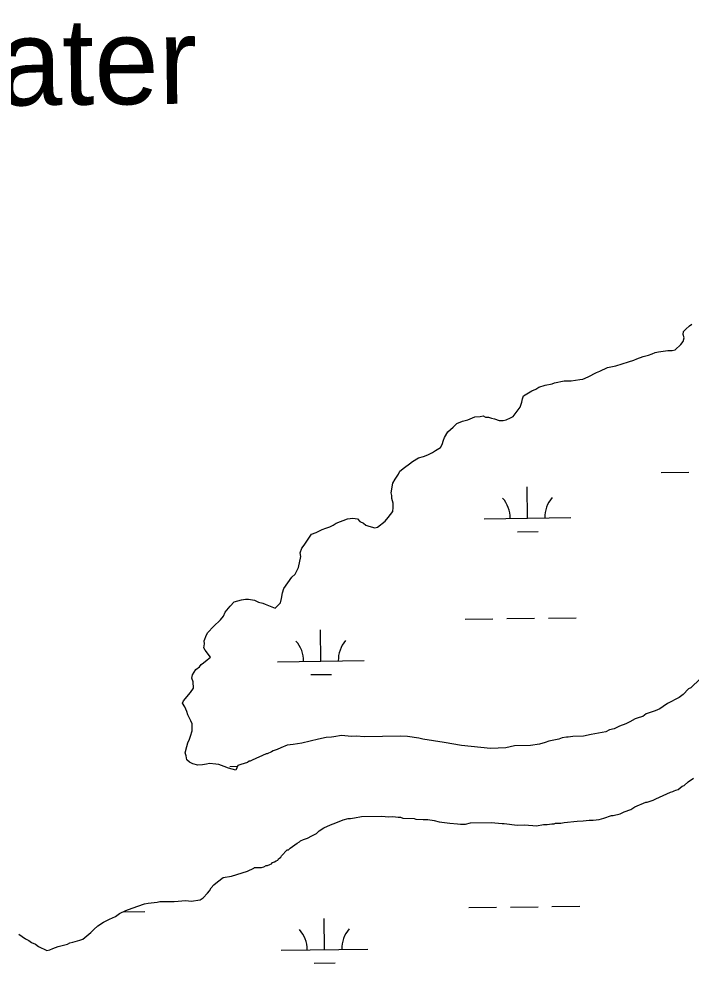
# Model space of a CAD drawing. Extents: x 3702978 to 3741108, y 397120 to 422907.
# Drawn here: x 3712893 to 3713669, y 405307 to 406396 of the extents above; entities that cross this region are included whole.
import ezdxf

# ---------------------------------------------------------------- set-up
doc = ezdxf.new("R2010")
doc.units = 0
for name, color, linetype in [('V-RIVR-IDEN', 7, 'Continuous'), ('V-TOPO-SHOR', 7, 'Continuous'), ('V-WETL-SWMP', 7, 'Continuous')]:
    doc.layers.add(name, color=color, linetype=linetype)

msp = doc.modelspace()

# ---------------------------------------------------------------- linework, layer by layer
at = {"layer": 'V-TOPO-SHOR'}
for points in [[(3713360.082, 405891.456), (3713364.814, 405893.586), (3713370.215, 405896.409), (3713373.585, 405898.514), (3713379.655, 405902.03), (3713381.638, 405905.473), (3713382.915, 405910.266), (3713384.216, 405913.697), (3713388.194, 405919.902), (3713394.227, 405925.462), (3713398.241, 405929.623), (3713405.005, 405932.47), (3713411.112, 405933.943), (3713419.226, 405937.496), (3713425.357, 405937.606), (3713428.751, 405938.349), (3713431.501, 405937.035), (3713434.907, 405937.096), (3713438.338, 405935.795), (3713441.757, 405935.175), (3713447.243, 405933.229), (3713452.012, 405933.314), (3713455.406, 405934.057), (3713460.139, 405936.186), (3713463.52, 405937.61), (3713471.5, 405948.657), (3713473.446, 405954.144), (3713474.054, 405958.244), (3713475.355, 405961.674), (3713484.795, 405967.296), (3713489.527, 405969.425), (3713492.897, 405971.53), (3713500.354, 405973.709), (3713508.505, 405975.218), (3713511.205, 405976.629), (3713522.069, 405978.869), (3713530.244, 405979.016), (3713540.438, 405980.562), (3713543.845, 405980.623), (3713549.927, 405983.458), (3713559.379, 405988.398), (3713563.442, 405989.834), (3713572.225, 405994.081), (3713581.726, 405996.296), (3713596.641, 406000.652), (3713602.736, 406002.806), (3713606.117, 406004.23), (3713613.562, 406007.089), (3713619.669, 406008.562), (3713623.732, 406009.998), (3713627.114, 406011.422), (3713631.19, 406012.176), (3713642.065, 406013.735), (3713646.834, 406013.82), (3713650.228, 406014.563), (3713656.931, 406020.816), (3713659.595, 406024.272), (3713660.884, 406028.384), (3713659.448, 406032.447), (3713660.068, 406035.865), (3713662.744, 406038.639), (3713666.771, 406042.119), (3713669.459, 406044.212)], [(3713143.293, 405529.863), (3713134.825, 405532.359), (3713130.02, 405534.317), (3713123.851, 405536.251), (3713120.433, 405536.871), (3713112.927, 405537.417), (3713109.533, 405536.675), (3713104.776, 405535.908), (3713099.326, 405535.81), (3713093.851, 405537.075), (3713089.727, 405539.045), (3713086.953, 405541.721), (3713086.186, 405546.478), (3713084.763, 405549.86), (3713086.672, 405557.391), (3713087.961, 405561.503), (3713089.931, 405565.627), (3713091.233, 405569.058), (3713093.166, 405575.226), (3713093.02, 405583.401), (3713091.596, 405586.783), (3713088.067, 405593.534), (3713086.631, 405597.597), (3713084.49, 405603.011), (3713081.691, 405607.049), (3713083.005, 405609.799), (3713091.009, 405619.483), (3713094.329, 405624.313), (3713094.195, 405631.807), (3713092.759, 405635.871), (3713093.367, 405639.97), (3713097.344, 405646.175), (3713101.383, 405648.974), (3713103.378, 405651.735), (3713106.066, 405653.828), (3713110.093, 405657.308), (3713114.131, 405660.106), (3713107.853, 405668.171), (3713106.442, 405670.872), (3713107.037, 405675.653), (3713106.976, 405679.059), (3713109.579, 405685.921), (3713110.893, 405688.67), (3713117.583, 405695.605), (3713125.623, 405703.246), (3713128.956, 405707.395), (3713130.915, 405712.2), (3713136.924, 405719.123), (3713141.607, 405723.978), (3713149.745, 405726.168), (3713154.502, 405726.935), (3713157.908, 405726.996), (3713164.745, 405725.756), (3713169.551, 405723.798), (3713174.344, 405722.521), (3713177.094, 405721.207), (3713188.761, 405716.646), (3713194.782, 405722.888), (3713196.059, 405727.681), (3713197.299, 405734.518), (3713198.576, 405739.312), (3713207.881, 405752.427), (3713211.908, 405755.907), (3713215.861, 405763.474), (3713218.354, 405776.467), (3713217.599, 405780.542), (3713219.545, 405786.029), (3713222.209, 405789.484), (3713230.845, 405801.906), (3713236.258, 405804.048), (3713243.01, 405807.576), (3713247.073, 405809.012), (3713251.817, 405810.46), (3713255.868, 405812.578), (3713259.238, 405814.682), (3713272.096, 405819.684), (3713278.215, 405820.475), (3713283.678, 405819.892), (3713286.464, 405816.534), (3713290.588, 405814.564), (3713293.35, 405812.569), (3713296.781, 405811.268), (3713303.63, 405809.346), (3713307.024, 405810.089), (3713315.758, 405817.06), (3713319.091, 405821.209), (3713324.419, 405828.12), (3713325.015, 405832.901), (3713324.929, 405837.669), (3713323.469, 405843.095), (3713323.408, 405846.501), (3713322.665, 405849.895), (3713324.513, 405860.832), (3713327.153, 405865.65), (3713331.142, 405871.174), (3713332.444, 405874.604), (3713337.821, 405878.79), (3713343.879, 405882.988), (3713347.236, 405885.774), (3713353.975, 405889.984), (3713360.082, 405891.456)], [(3713679.025, 405635.4), (3713668.308, 405624.986), (3713665.608, 405623.574), (3713659.586, 405617.333), (3713654.879, 405613.841), (3713641.376, 405606.784), (3713636.668, 405603.292), (3713632.629, 405600.493), (3713627.216, 405598.351), (3713617.058, 405594.762), (3713613.02, 405591.963), (3713608.956, 405590.527), (3713604.212, 405589.079), (3713598.142, 405585.563), (3713593.41, 405583.433), (3713585.965, 405580.574), (3713579.882, 405577.739), (3713574.457, 405576.278), (3713570.406, 405574.161), (3713553.423, 405571.13), (3713544.603, 405568.927), (3713532.341, 405568.707), (3713526.903, 405567.928), (3713524.859, 405567.891), (3713520.102, 405567.124), (3713516.039, 405565.689), (3713504.494, 405563.437), (3713500.431, 405562.001), (3713493.655, 405559.835), (3713483.461, 405558.289), (3713465.067, 405557.958), (3713454.884, 405555.731), (3713437.184, 405554.732), (3713403.728, 405558.22), (3713383.898, 405561.953), (3713359.299, 405565.6), (3713354.506, 405566.877), (3713341.525, 405568.689), (3713333.338, 405569.223), (3713291.781, 405568.477), (3713282.231, 405568.987), (3713276.781, 405568.889), (3713265.175, 405570.044), (3713256.343, 405568.522), (3713253.63, 405567.792), (3713247.499, 405567.682), (3713238.679, 405565.479), (3713219.677, 405561.049), (3713209.482, 405559.503), (3713202.682, 405558.699), (3713195.237, 405555.84), (3713191.186, 405553.722), (3713186.442, 405552.274), (3713184.422, 405550.875), (3713179.69, 405548.746), (3713178.328, 405548.721), (3713162.1, 405541.615), (3713160.08, 405540.216), (3713158.718, 405540.191), (3713156.699, 405538.792), (3713149.241, 405536.614), (3713145.859, 405535.19), (3713143.293, 405529.863)], [(3713226.22, 405451.393), (3713230.94, 405454.203), (3713236.341, 405457.026), (3713239.698, 405459.813), (3713245.087, 405463.317), (3713252.52, 405466.858), (3713258.615, 405469.012), (3713267.41, 405472.577), (3713272.836, 405474.037), (3713275.561, 405474.086), (3713280.317, 405474.853), (3713288.468, 405476.362), (3713311.631, 405476.778), (3713319.819, 405476.244), (3713324.587, 405476.329), (3713330.731, 405475.758), (3713333.456, 405475.807), (3713336.206, 405474.494), (3713349.162, 405474.045), (3713351.218, 405473.4), (3713359.405, 405472.866), (3713364.855, 405472.964), (3713372.374, 405471.736), (3713377.848, 405470.471), (3713390.148, 405468.647), (3713399.016, 405468.125), (3713402.435, 405467.505), (3713408.566, 405467.615), (3713413.992, 405469.075), (3713437.836, 405469.504), (3713450.805, 405468.373), (3713452.849, 405468.41), (3713467.873, 405466.635), (3713476.048, 405466.782), (3713486.279, 405466.284), (3713490.379, 405465.677), (3713498.53, 405467.186), (3713502.618, 405467.259), (3713508.055, 405468.038), (3713510.78, 405468.087), (3713512.131, 405468.793), (3713518.262, 405468.903), (3713522.337, 405469.658), (3713537.301, 405471.289), (3713544.113, 405471.412), (3713550.914, 405472.215), (3713555.683, 405472.301), (3713562.483, 405473.104), (3713567.909, 405474.565), (3713576.716, 405477.449), (3713578.76, 405477.486), (3713586.899, 405479.676), (3713591.631, 405481.806), (3713599.076, 405484.665), (3713603.796, 405487.476), (3713616.642, 405493.158), (3713618.004, 405493.183), (3713622.749, 405494.631), (3713624.78, 405495.349), (3713628.162, 405496.773), (3713645.059, 405504.572), (3713647.772, 405505.303), (3713649.122, 405506.008), (3713651.154, 405506.726), (3713653.867, 405507.456), (3713658.562, 405511.63), (3713660.594, 405512.348), (3713665.289, 405516.521), (3713671.347, 405520.719)], [(3712892.934, 405340.608), (3712900.525, 405335.292), (3712904.65, 405333.322), (3712907.412, 405331.327), (3712912.217, 405329.369), (3712915.672, 405326.705), (3712925.296, 405322.107), (3712928.69, 405322.849), (3712932.072, 405324.273), (3712938.166, 405326.427), (3712949.018, 405329.348), (3712951.718, 405330.759), (3712955.112, 405331.502), (3712963.251, 405333.692), (3712966.633, 405335.116), (3712976.036, 405342.781), (3712979.381, 405346.249), (3712984.076, 405350.422), (3712990.816, 405354.632), (3712997.567, 405358.16), (3713004.331, 405361.008), (3713009.038, 405364.5), (3713016.471, 405368.041), (3713023.916, 405370.9), (3713038.137, 405375.926), (3713042.213, 405376.681), (3713052.419, 405377.545), (3713055.813, 405378.288), (3713072.164, 405378.581), (3713085.777, 405379.507), (3713091.92, 405378.936), (3713102.115, 405380.482), (3713105.484, 405382.587), (3713110.837, 405388.135), (3713112.832, 405390.897), (3713114.814, 405394.34), (3713118.159, 405397.807), (3713122.186, 405401.287), (3713128.913, 405406.178), (3713138.426, 405407.712), (3713156.722, 405413.492), (3713164.155, 405417.033), (3713164.894, 405417.646), (3713172.987, 405417.726), (3713175.7, 405418.456), (3713178.401, 405419.867), (3713179.763, 405419.892), (3713182.464, 405421.303), (3713184.495, 405422.021), (3713185.833, 405423.408), (3713187.865, 405424.126), (3713189.884, 405425.525), (3713191.916, 405426.243), (3713192.573, 405427.618), (3713195.261, 405429.711), (3713195.918, 405431.086), (3713202.608, 405438.021), (3713203.971, 405438.045), (3713205.978, 405440.126), (3713214.055, 405445.723), (3713216.756, 405447.134), (3713218.094, 405448.521), (3713221.476, 405449.945), (3713226.22, 405451.393)]]:
    msp.add_lwpolyline(points, dxfattribs=at)
at = {"layer": 'V-WETL-SWMP'}
for p, q in [((3713634.005, 405873.133), (3713666.002, 405873.53)), ((3713480.055, 405820.474), (3713479.608, 405856.472)), ((3713430.059, 405819.853), (3713530.051, 405821.095)), ((3713468.248, 405804.896), (3713492.246, 405805.194)), ((3713408.086, 405704.14), (3713440.084, 405704.537)), ((3713456.083, 405704.736), (3713488.08, 405705.133)), ((3713504.079, 405705.332), (3713536.077, 405705.729)), ((3713241.612, 405655.638), (3713241.165, 405691.635)), ((3713191.616, 405655.017), (3713291.608, 405656.259)), ((3713229.805, 405640.059), (3713253.803, 405640.357)), ((3713136.268, 405534.249), (3713145.461, 405534.363)), ((3713013.309, 405366.534), (3713038.34, 405366.845)), ((3713412.219, 405371.49), (3713444.216, 405371.887)), ((3713460.215, 405372.086), (3713492.213, 405372.483)), ((3713508.211, 405372.682), (3713540.209, 405373.08)), ((3713245.744, 405322.988), (3713245.297, 405358.985)), ((3713195.748, 405322.367), (3713295.741, 405323.609)), ((3713233.937, 405307.409), (3713257.935, 405307.707))]:
    msp.add_line(p, q, dxfattribs=at)
for points in [[(3713360.082, 405891.456), (3713364.814, 405893.586), (3713370.215, 405896.409), (3713373.585, 405898.514), (3713379.655, 405902.03), (3713381.638, 405905.473), (3713382.915, 405910.266), (3713384.216, 405913.697), (3713388.194, 405919.902), (3713394.227, 405925.462), (3713398.241, 405929.623), (3713405.005, 405932.47), (3713411.112, 405933.943), (3713419.226, 405937.496), (3713425.357, 405937.606), (3713428.751, 405938.349), (3713431.501, 405937.035), (3713434.907, 405937.096), (3713438.338, 405935.795), (3713441.757, 405935.175), (3713447.243, 405933.229), (3713452.012, 405933.314), (3713455.406, 405934.057), (3713460.139, 405936.186), (3713463.52, 405937.61), (3713471.5, 405948.657), (3713473.446, 405954.144), (3713474.054, 405958.244), (3713475.355, 405961.674), (3713484.795, 405967.296), (3713489.527, 405969.425), (3713492.897, 405971.53), (3713500.354, 405973.709), (3713508.505, 405975.218), (3713511.205, 405976.629), (3713522.069, 405978.869), (3713530.244, 405979.016), (3713540.438, 405980.562), (3713543.845, 405980.623), (3713549.927, 405983.458), (3713559.379, 405988.398), (3713563.442, 405989.834), (3713572.225, 405994.081), (3713581.726, 405996.296), (3713596.641, 406000.652), (3713602.736, 406002.806), (3713606.117, 406004.23), (3713613.562, 406007.089), (3713619.669, 406008.562), (3713623.732, 406009.998), (3713627.114, 406011.422), (3713631.19, 406012.176), (3713642.065, 406013.735), (3713646.834, 406013.82), (3713650.228, 406014.563), (3713656.931, 406020.816), (3713659.595, 406024.272), (3713660.884, 406028.384), (3713659.448, 406032.447), (3713660.068, 406035.865), (3713662.744, 406038.639), (3713666.771, 406042.119), (3713669.459, 406044.212)], [(3713143.293, 405529.863), (3713134.825, 405532.359), (3713130.02, 405534.317), (3713123.851, 405536.251), (3713120.433, 405536.871), (3713112.927, 405537.417), (3713109.533, 405536.675), (3713104.776, 405535.908), (3713099.326, 405535.81), (3713093.851, 405537.075), (3713089.727, 405539.045), (3713086.953, 405541.721), (3713086.186, 405546.478), (3713084.763, 405549.86), (3713086.672, 405557.391), (3713087.961, 405561.503), (3713089.931, 405565.627), (3713091.233, 405569.058), (3713093.166, 405575.226), (3713093.02, 405583.401), (3713091.596, 405586.783), (3713088.067, 405593.534), (3713086.631, 405597.597), (3713084.49, 405603.011), (3713081.691, 405607.049), (3713083.005, 405609.799), (3713091.009, 405619.483), (3713094.329, 405624.313), (3713094.195, 405631.807), (3713092.759, 405635.871), (3713093.367, 405639.97), (3713097.344, 405646.175), (3713101.383, 405648.974), (3713103.378, 405651.735), (3713106.066, 405653.828), (3713110.093, 405657.308), (3713114.131, 405660.106), (3713107.853, 405668.171), (3713106.442, 405670.872), (3713107.037, 405675.653), (3713106.976, 405679.059), (3713109.579, 405685.921), (3713110.893, 405688.67), (3713117.583, 405695.605), (3713125.623, 405703.246), (3713128.956, 405707.395), (3713130.915, 405712.2), (3713136.924, 405719.123), (3713141.607, 405723.978), (3713149.745, 405726.168), (3713154.502, 405726.935), (3713157.908, 405726.996), (3713164.745, 405725.756), (3713169.551, 405723.798), (3713174.344, 405722.521), (3713177.094, 405721.207), (3713188.761, 405716.646), (3713194.782, 405722.888), (3713196.059, 405727.681), (3713197.299, 405734.518), (3713198.576, 405739.312), (3713207.881, 405752.427), (3713211.908, 405755.907), (3713215.861, 405763.474), (3713218.354, 405776.467), (3713217.599, 405780.542), (3713219.545, 405786.029), (3713222.209, 405789.484), (3713230.845, 405801.906), (3713236.258, 405804.048), (3713243.01, 405807.576), (3713247.073, 405809.012), (3713251.817, 405810.46), (3713255.868, 405812.578), (3713259.238, 405814.682), (3713272.096, 405819.684), (3713278.215, 405820.475), (3713283.678, 405819.892), (3713286.464, 405816.534), (3713290.588, 405814.564), (3713293.35, 405812.569), (3713296.781, 405811.268), (3713303.63, 405809.346), (3713307.024, 405810.089), (3713315.758, 405817.06), (3713319.091, 405821.209), (3713324.419, 405828.12), (3713325.015, 405832.901), (3713324.929, 405837.669), (3713323.469, 405843.095), (3713323.408, 405846.501), (3713322.665, 405849.895), (3713324.513, 405860.832), (3713327.153, 405865.65), (3713331.142, 405871.174), (3713332.444, 405874.604), (3713337.821, 405878.79), (3713343.879, 405882.988), (3713347.236, 405885.774), (3713353.975, 405889.984), (3713360.082, 405891.456)], [(3713679.025, 405635.4), (3713668.308, 405624.986), (3713665.608, 405623.574), (3713659.586, 405617.333), (3713654.879, 405613.841), (3713641.376, 405606.784), (3713636.668, 405603.292), (3713632.629, 405600.493), (3713627.216, 405598.351), (3713617.058, 405594.762), (3713613.02, 405591.963), (3713608.956, 405590.527), (3713604.212, 405589.079), (3713598.142, 405585.563), (3713593.41, 405583.433), (3713585.965, 405580.574), (3713579.882, 405577.739), (3713574.457, 405576.278), (3713570.406, 405574.161), (3713553.423, 405571.13), (3713544.603, 405568.927), (3713532.341, 405568.707), (3713526.903, 405567.928), (3713524.859, 405567.891), (3713520.102, 405567.124), (3713516.039, 405565.689), (3713504.494, 405563.437), (3713500.431, 405562.001), (3713493.655, 405559.835), (3713483.461, 405558.289), (3713465.067, 405557.958), (3713454.884, 405555.731), (3713437.184, 405554.732), (3713403.728, 405558.22), (3713383.898, 405561.953), (3713359.299, 405565.6), (3713354.506, 405566.877), (3713341.525, 405568.689), (3713333.338, 405569.223), (3713291.781, 405568.477), (3713282.231, 405568.987), (3713276.781, 405568.889), (3713265.175, 405570.044), (3713256.343, 405568.522), (3713253.63, 405567.792), (3713247.499, 405567.682), (3713238.679, 405565.479), (3713219.677, 405561.049), (3713209.482, 405559.503), (3713202.682, 405558.699), (3713195.237, 405555.84), (3713191.186, 405553.722), (3713186.442, 405552.274), (3713184.422, 405550.875), (3713179.69, 405548.746), (3713178.328, 405548.721), (3713162.1, 405541.615), (3713160.08, 405540.216), (3713158.718, 405540.191), (3713156.699, 405538.792), (3713149.241, 405536.614), (3713145.859, 405535.19), (3713143.293, 405529.863)], [(3713226.22, 405451.393), (3713230.94, 405454.203), (3713236.341, 405457.026), (3713239.698, 405459.813), (3713245.087, 405463.317), (3713252.52, 405466.858), (3713258.615, 405469.012), (3713267.41, 405472.577), (3713272.836, 405474.037), (3713275.561, 405474.086), (3713280.317, 405474.853), (3713288.468, 405476.362), (3713311.631, 405476.778), (3713319.819, 405476.244), (3713324.587, 405476.329), (3713330.731, 405475.758), (3713333.456, 405475.807), (3713336.206, 405474.494), (3713349.162, 405474.045), (3713351.218, 405473.4), (3713359.405, 405472.866), (3713364.855, 405472.964), (3713372.374, 405471.736), (3713377.848, 405470.471), (3713390.148, 405468.647), (3713399.016, 405468.125), (3713402.435, 405467.505), (3713408.566, 405467.615), (3713413.992, 405469.075), (3713437.836, 405469.504), (3713450.805, 405468.373), (3713452.849, 405468.41), (3713467.873, 405466.635), (3713476.048, 405466.782), (3713486.279, 405466.284), (3713490.379, 405465.677), (3713498.53, 405467.186), (3713502.618, 405467.259), (3713508.055, 405468.038), (3713510.78, 405468.087), (3713512.131, 405468.793), (3713518.262, 405468.903), (3713522.337, 405469.658), (3713537.301, 405471.289), (3713544.113, 405471.412), (3713550.914, 405472.215), (3713555.683, 405472.301), (3713562.483, 405473.104), (3713567.909, 405474.565), (3713576.716, 405477.449), (3713578.76, 405477.486), (3713586.899, 405479.676), (3713591.631, 405481.806), (3713599.076, 405484.665), (3713603.796, 405487.476), (3713616.642, 405493.158), (3713618.004, 405493.183), (3713622.749, 405494.631), (3713624.78, 405495.349), (3713628.162, 405496.773), (3713645.059, 405504.572), (3713647.772, 405505.303), (3713649.122, 405506.008), (3713651.154, 405506.726), (3713653.867, 405507.456), (3713658.562, 405511.63), (3713660.594, 405512.348), (3713665.289, 405516.521), (3713671.347, 405520.719)], [(3712892.934, 405340.608), (3712900.525, 405335.292), (3712904.65, 405333.322), (3712907.412, 405331.327), (3712912.217, 405329.369), (3712915.672, 405326.705), (3712925.296, 405322.107), (3712928.69, 405322.849), (3712932.072, 405324.273), (3712938.166, 405326.427), (3712949.018, 405329.348), (3712951.718, 405330.759), (3712955.112, 405331.502), (3712963.251, 405333.692), (3712966.633, 405335.116), (3712976.036, 405342.781), (3712979.381, 405346.249), (3712984.076, 405350.422), (3712990.816, 405354.632), (3712997.567, 405358.16), (3713004.331, 405361.008), (3713009.038, 405364.5), (3713016.471, 405368.041), (3713023.916, 405370.9), (3713038.137, 405375.926), (3713042.213, 405376.681), (3713052.419, 405377.545), (3713055.813, 405378.288), (3713072.164, 405378.581), (3713085.777, 405379.507), (3713091.92, 405378.936), (3713102.115, 405380.482), (3713105.484, 405382.587), (3713110.837, 405388.135), (3713112.832, 405390.897), (3713114.814, 405394.34), (3713118.159, 405397.807), (3713122.186, 405401.287), (3713128.913, 405406.178), (3713138.426, 405407.712), (3713156.722, 405413.492), (3713164.155, 405417.033), (3713164.894, 405417.646), (3713172.987, 405417.726), (3713175.7, 405418.456), (3713178.401, 405419.867), (3713179.763, 405419.892), (3713182.464, 405421.303), (3713184.495, 405422.021), (3713185.833, 405423.408), (3713187.865, 405424.126), (3713189.884, 405425.525), (3713191.916, 405426.243), (3713192.573, 405427.618), (3713195.261, 405429.711), (3713195.918, 405431.086), (3713202.608, 405438.021), (3713203.971, 405438.045), (3713205.978, 405440.126), (3713214.055, 405445.723), (3713216.756, 405447.134), (3713218.094, 405448.521), (3713221.476, 405449.945), (3713226.22, 405451.393)]]:
    msp.add_lwpolyline(points, dxfattribs=at)
for centre, start, end in [((3713535.288, 405821.635), 139.93988, 181.483539), ((3713424.81, 405820.263), 359.939883, 41.483542), ((3713186.368, 405655.427), 359.939883, 41.483542), ((3713296.845, 405656.799), 139.93988, 181.483539), ((3713190.5, 405322.777), 359.939883, 41.483542), ((3713300.977, 405324.149), 139.93988, 181.483539)]:
    msp.add_arc(centre, 35.246, start, end, dxfattribs=at)

# ---------------------------------------------------------------- texts
at = {"layer": 'V-RIVR-IDEN'}
msp.add_text('Water', height=99.9998, rotation=0.572928, dxfattribs=at).set_placement((3712742.657, 406294.999))

doc.saveas('drawing.dxf')
